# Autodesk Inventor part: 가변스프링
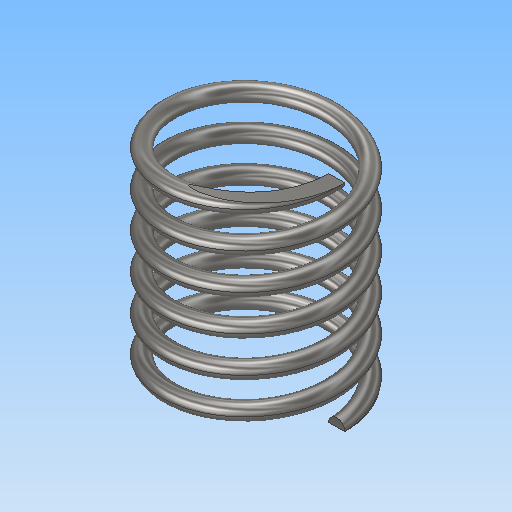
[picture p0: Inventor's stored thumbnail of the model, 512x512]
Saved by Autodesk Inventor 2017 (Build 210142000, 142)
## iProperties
Part Number: 가변스프링
Material: 스테인레스 스틸
Document SubType Name: Modeling
Designer: 7-1
Density: 8 g/cm^3
Appearance: 반연마
Mass: 9.32422 g
Surface Area: 23.6259 cm^2
Volume: 1.16553 cm^3
Author: 7-1
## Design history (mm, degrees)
sketch "스케치1"
  geometry: L1 (0, 0)-(0, 26.7); L2 (0, 26.7)-(39.861, 26.7); C1 r 1 at (10, 0)
  constraints: 4 end point, 1 centre point, 1 horizontal alignment, 1 perpendicular, 1 vertical
  dimensions: "d0" = 26.7 distance of L1.start L1.end (derived); "d1" = 2 diameter of C1; "d2" = 20 diameter of C1.centre L1
feature "코일1" sketch "스케치1" pitch "d3" = 10; turns "d5" = 6; dims "d4" = 26.7 (= d0), "d6" = 0, angle "d7" = 90 deg, angle "d8" = 90 deg, "d9" = 0, "d10" = 0
sketch "스케치2"
  geometry: L1 (0, 13.611)-(26.7, 13.611); L2 (26.7, 13.611)-(26.7, -13.611); L3 (26.7, -13.611)-(0, -13.611); L4 (0, -13.611)-(0, 13.611); 2 further points
  constraints: 8 end point, 2 parallel, 1 coincident, 1 horizontal, 1 midpoint, 1 perpendicular
  dimensions: "d11" = 26.7 distance of L2.end L3.end (derived); "d12" = 27.22222 distance of L1.end L2.end
extrude "돌출1" sketch "스케치2" stored distance "d13" = 10; taper "d14" = 0 deg
node "솔리드1"
